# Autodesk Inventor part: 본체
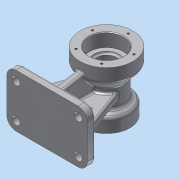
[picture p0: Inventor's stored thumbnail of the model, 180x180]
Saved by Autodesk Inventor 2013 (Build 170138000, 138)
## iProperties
Created: 2015-08
Part Number: 본체
Material: 알루미늄 6061
Document SubType Name: Modeling
Designer: Administrator
Density: 2.71 g/cm^3
Mass: 1062.79 g
Surface Area: 749.652 cm^2
Volume: 392.172 cm^3
Author: Administrator
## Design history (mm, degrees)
sketch "스케치2"
  geometry: L1 (0, 0)-(0, -90); L2 (0, 0)-(40, 0); L3 (35, -90)-(0, -90); L4 (40, 0)-(40, -20); L5 (40, -20)-(26, -36.685); L6 (26, -36.685)-(26, -64.804); L7 (26, -64.804)-(35, -70); L8 (35, -70)-(35, -90)
  constraints: 16 end point, 3 perpendicular, 2 parallel, 1 vertical
  dimensions: "d0" = 90 distance of L1.start L1.end; "d2" = 40 deg angle of L6 L5; "d3" = 60 deg angle of L6 L7; "d4" = 20 distance of L2.end L4.end; "d5" = 20 distance of L7.end L3.start; "d6" = 80 diameter of L4 L1; "d7" = 70 diameter of L8 L1; "d8" = 52 diameter of L6 L1
revolve "회전1" sketch "스케치2" stored, may be unused: angle "d9" = 90 deg
node "작업 평면1"
sketch "스케치3"
  geometry: L1 (61, -90)-(-61, -90); L2 (-61, -90)-(-61, -10); L3 (-61, -10)-(61, -10); L4 (61, -10)-(61, -90); L5 (-35, -90)-(35, -90) reference; L6 (-35, -70)-(35, -70) reference; 2 further points
  constraints: 8 end point, 2 midpoint, 2 parallel, 1 horizontal, 1 perpendicular
  dimensions: "d11" = 122 distance of L1.start L1.end; "d13" = 80 distance of L1.end L2.end
extrude "돌출1" join sketch "스케치3" distance "d14" = 12; taper "d15" = 0 deg
fillet "모깎기1" dims "d16" = 14
node "작업 평면2"
sketch "스케치5"
  geometry: L1 (61, -90)-(-61, -90) reference; L2 (-61, -90)-(-61, -78) reference; L3 (-61, -78)-(61, -78) reference; L4 (61, -78)-(61, -90) reference; L5 (-51, -78)-(-25.091, -6.815); L6 (25.091, -6.815)-(51, -78); A1 r 26 centre (0, 0) between (-25.091, -6.815) and (25.091, -6.815) reference; 1 further point
  constraints: 4 end point, 2 point on circle, 2 point on line
  dimensions: "d18" = 10 distance of L5.start L2.end; "d19" = 10 distance of L3.end L6.end; "d20" = 70 deg angle of L3 L6; "d22" = 70 deg angle of L3 L5
extrude "돌출2" join sketch "스케치5" stored distance "d23" = 12; taper "d24" = 0 deg
sketch "스케치6"
  geometry: L1 (-40, 0)-(40, 0) reference; L2 (40, 0)-(40, -20) reference; L3 (40, -20)-(26, -36.685) reference; L4 (26, -36.685)-(26, -64.804) reference; L5 (26, -64.804)-(35, -70) reference; L6 (35, -70)-(35, -90) reference; L7 (35, -90)-(-35, -90) reference; L8 (-35, -90)-(-35, -70) reference; L9 (-35, -70)-(-26, -64.804) reference; L10 (-26, -64.804)-(-26, -56) reference; L11 (-26, -56)-(-78, -56) reference; L12 (-78, -56)-(-78, -90) reference; L13 (-78, -90)-(-90, -90) reference; L14 (-90, -90)-(-90, -10) reference; L15 (-90, -10)-(-78, -10) reference; L16 (-78, -10)-(-78, -44) reference; L17 (-78, -44)-(-26, -44) reference; L18 (-26, -44)-(-26, -36.685) reference; L19 (-26, -36.685)-(-40, -20) reference; L20 (-40, -20)-(-40, 0) reference; L21 (-35, -80)-(-78, -80); L22 (-78, -20)-(-40, -13.3); 1 further point
  constraints: 4 end point, 3 point on line, 1 midpoint, 1 perpendicular
  dimensions: "d25" = 10 distance between parallel lines of L13 L21; "d26" = 10 distance of L15.end L22.start; "d27" = 80 deg angle of L16 L22
  node "절단 모서리 투영3"
feature "리브1" dims "d28" = 1, "d29" = 12, "d30" = 0, "d31" = 0, "d32" = 1, "d33" = 1
feature "리브2" dims "d34" = 1, "d35" = 12, "d36" = 0, "d37" = 0, "d38" = 1, "d39" = 1
hole "구멍1" diameter "d42" = 38; stored, may be unused: countersink angle "d46" = 90 deg, drill point angle "d48" = 0 deg; dims "d40" = 10, "d41" = 10, "d43" = 6, "d44" = 52, "d45" = 20, "d47" = 23
sketch "스케치7"
  geometry: C1 r 35 at (0, 0) reference; 1 further point
  constraints: 1 coincident
hole "구멍2" sketch "스케치7" at (0, 0) diameter "d49" = 32; stored, may be unused: countersink angle "d53" = 90 deg, drill point angle "d55" = 0 deg; dims "d50" = 6, "d51" = 40, "d52" = 17, "d54" = 23
fillet "모깎기2" dims "d56" = 0.3
fillet "모깎기3" dims "d57" = 3
chamfer "모따기1" distance "d58" = 1; stored, may be unused: second distance "d59" = 2, angle "d60" = 45 deg
sketch "스케치8" dims "d61" = 54
  geometry: C1 r 21 at (0, 0) reference; 2 further points
  constraints: 2 vertical alignment, 1 coincident, 2 other
hole "구멍3" sketch "스케치8" at (0, 27) diameter "d62" = 3.242; stored, may be unused: countersink angle "d66" = 90 deg, drill point angle "d68" = 118 deg; dims "d63" = 10, "d64" = 40, "d65" = 17, "d67" = 13
sketch "스케치9" dims "d72" = 66
  geometry: C1 r 27 at (0, 0) reference; 2 further points
  constraints: 2 vertical alignment, 1 coincident, 2 other
hole "구멍4" sketch "스케치9" at (0, 33) diameter "d73" = 3.242; stored, may be unused: countersink angle "d77" = 90 deg, drill point angle "d79" = 118 deg; dims "d74" = 10, "d75" = 40, "d76" = 17, "d78" = 13
sketch "스케치10"
  geometry: A1 r 14 centre (-47, 76) between (-47, 90) and (-61, 76) reference; A2 r 14 centre (-47, 24) between (-61, 24) and (-47, 10) reference; A3 r 14 centre (47, 24) between (47, 10) and (61, 24) reference; A4 r 14 centre (47, 76) between (61, 76) and (47, 90) reference; 5 further points
  constraints: 4 coincident
hole "구멍5" sketch "스케치10" at (-47, 76), (47, 76), (47, 24), (-47, 24) diameter "d83" = 12; stored, may be unused: countersink angle "d87" = 90 deg, drill point angle "d89" = 118 deg; dims "d84" = 10, "d85" = 40, "d86" = 17, "d88" = 13
sketch "스케치11"
  geometry: L1 (-6, -78)-(-51, -78) reference; L2 (-30, -54)-(-30, -60); L3 (-18, -54)-(-18, -60); A1 r 26 centre (0, 0) between (-25.091, -6.815) and (-6, -25.298) reference; A2 r 6 centre (-24, -54) between (-18, -54) and (-30, -54); A3 r 6 centre (-24, -60) between (-30, -60) and (-18, -60)
  constraints: 4 end point, 4 point on circle, 4 tangent, 2 centre point, 1 vertical alignment
  dimensions: "d90" = 12 diameter of A2; "d91" = 12 diameter of A3; "d92" = 18 dimension on A3 A2; "d93" = 18 distance from line of A3.centre L1; "d94" = 24 horizontal distance of A1.centre A2.centre
extrude "돌출3" cut sketch "스케치11" stored distance "d95" = 12; taper "d96" = 0 deg
fillet "모깎기4" dims "d97" = 3
fillet "모깎기5" dims "d98" = 3
fillet "모깎기6" dims "d99" = 5
fillet "모깎기7" dims "d100" = 3
fillet "모깎기8" dims "d101" = 3
sketch "스케치12"
  geometry: L1 (-10, -41.081)-(1, -41.081) reference; L2 (-3, -0.963)-(-3, -38.081) reference; 2 further points
  constraints: 1 other
  dimensions: "d102" = 24 distance from line of L1 point (13, -17.081); "d103" = 16 distance from line of point (13, -17.081) L2
feature "엠보싱1" sketch "스케치12" dims "d0" = 90, "d2" = 40 deg, "d3" = 60 deg, "d4" = 20, "d5" = 20, "d6" = 80, "d7" = 70, "d8" = 52, "d104" = 0.5, "d105" = 0
node "솔리드1"
pattern_circular "원형 패턴1" dims angle "d70" = 360 deg
pattern_circular "원형 패턴2" dims angle "d81" = 360 deg
mirror "대칭1"
node "투영된 루프1"
node "절단 모서리 투영2"
